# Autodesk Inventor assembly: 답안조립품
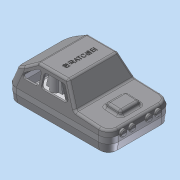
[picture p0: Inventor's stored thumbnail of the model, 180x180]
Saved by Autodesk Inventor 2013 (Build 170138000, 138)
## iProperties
Created: 2015-05
Part Number: 답안조립품
Document SubType Name: Assembly
Designer: Administrator
Author: Administrator
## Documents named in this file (7)
- C:\Users\Administrator\Desktop\450508V1049\답안조립품.iam
- C:\Users\Administrator\Desktop\450508V1049\본체.ipt
- C:\Users\Administrator\Desktop\450508V1049\M2x4.ipt
- C:\Users\Administrator\Desktop\450508V1049\M4x10.ipt
- C:\Users\Administrator\Desktop\450508V1049\바퀴.ipt
- C:\Users\Administrator\Desktop\450508V1049\바퀴고정부.ipt
- C:\Users\Administrator\Desktop\450508V1049\커버.ipt
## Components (20 placed, 2 different names)
1. M2x4:1
2. M4x10:1
3. M2x4:2
4. M2x4:3
5. M2x4:4
6. M2x4:5
7. M2x4:6
8. M2x4:7
9. M2x4:8
10. M2x4:9
11. M2x4:10
12. M2x4:11
13. M2x4:12
14. M2x4:13
15. M2x4:14
16. M2x4:15
17. M2x4:16
18. M4x10:2
19. M4x10:3
20. M4x10:4
